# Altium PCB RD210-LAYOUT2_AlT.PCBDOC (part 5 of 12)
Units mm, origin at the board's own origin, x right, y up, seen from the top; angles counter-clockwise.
Board outline 250 x 123 mm, 4 copper layers (TOP, Mid-Layer 1, Mid-Layer 2, BOTTOM), stack 0.711 mm thick; 1043 components, 659 nets, 2786 pads, 1228 vias.
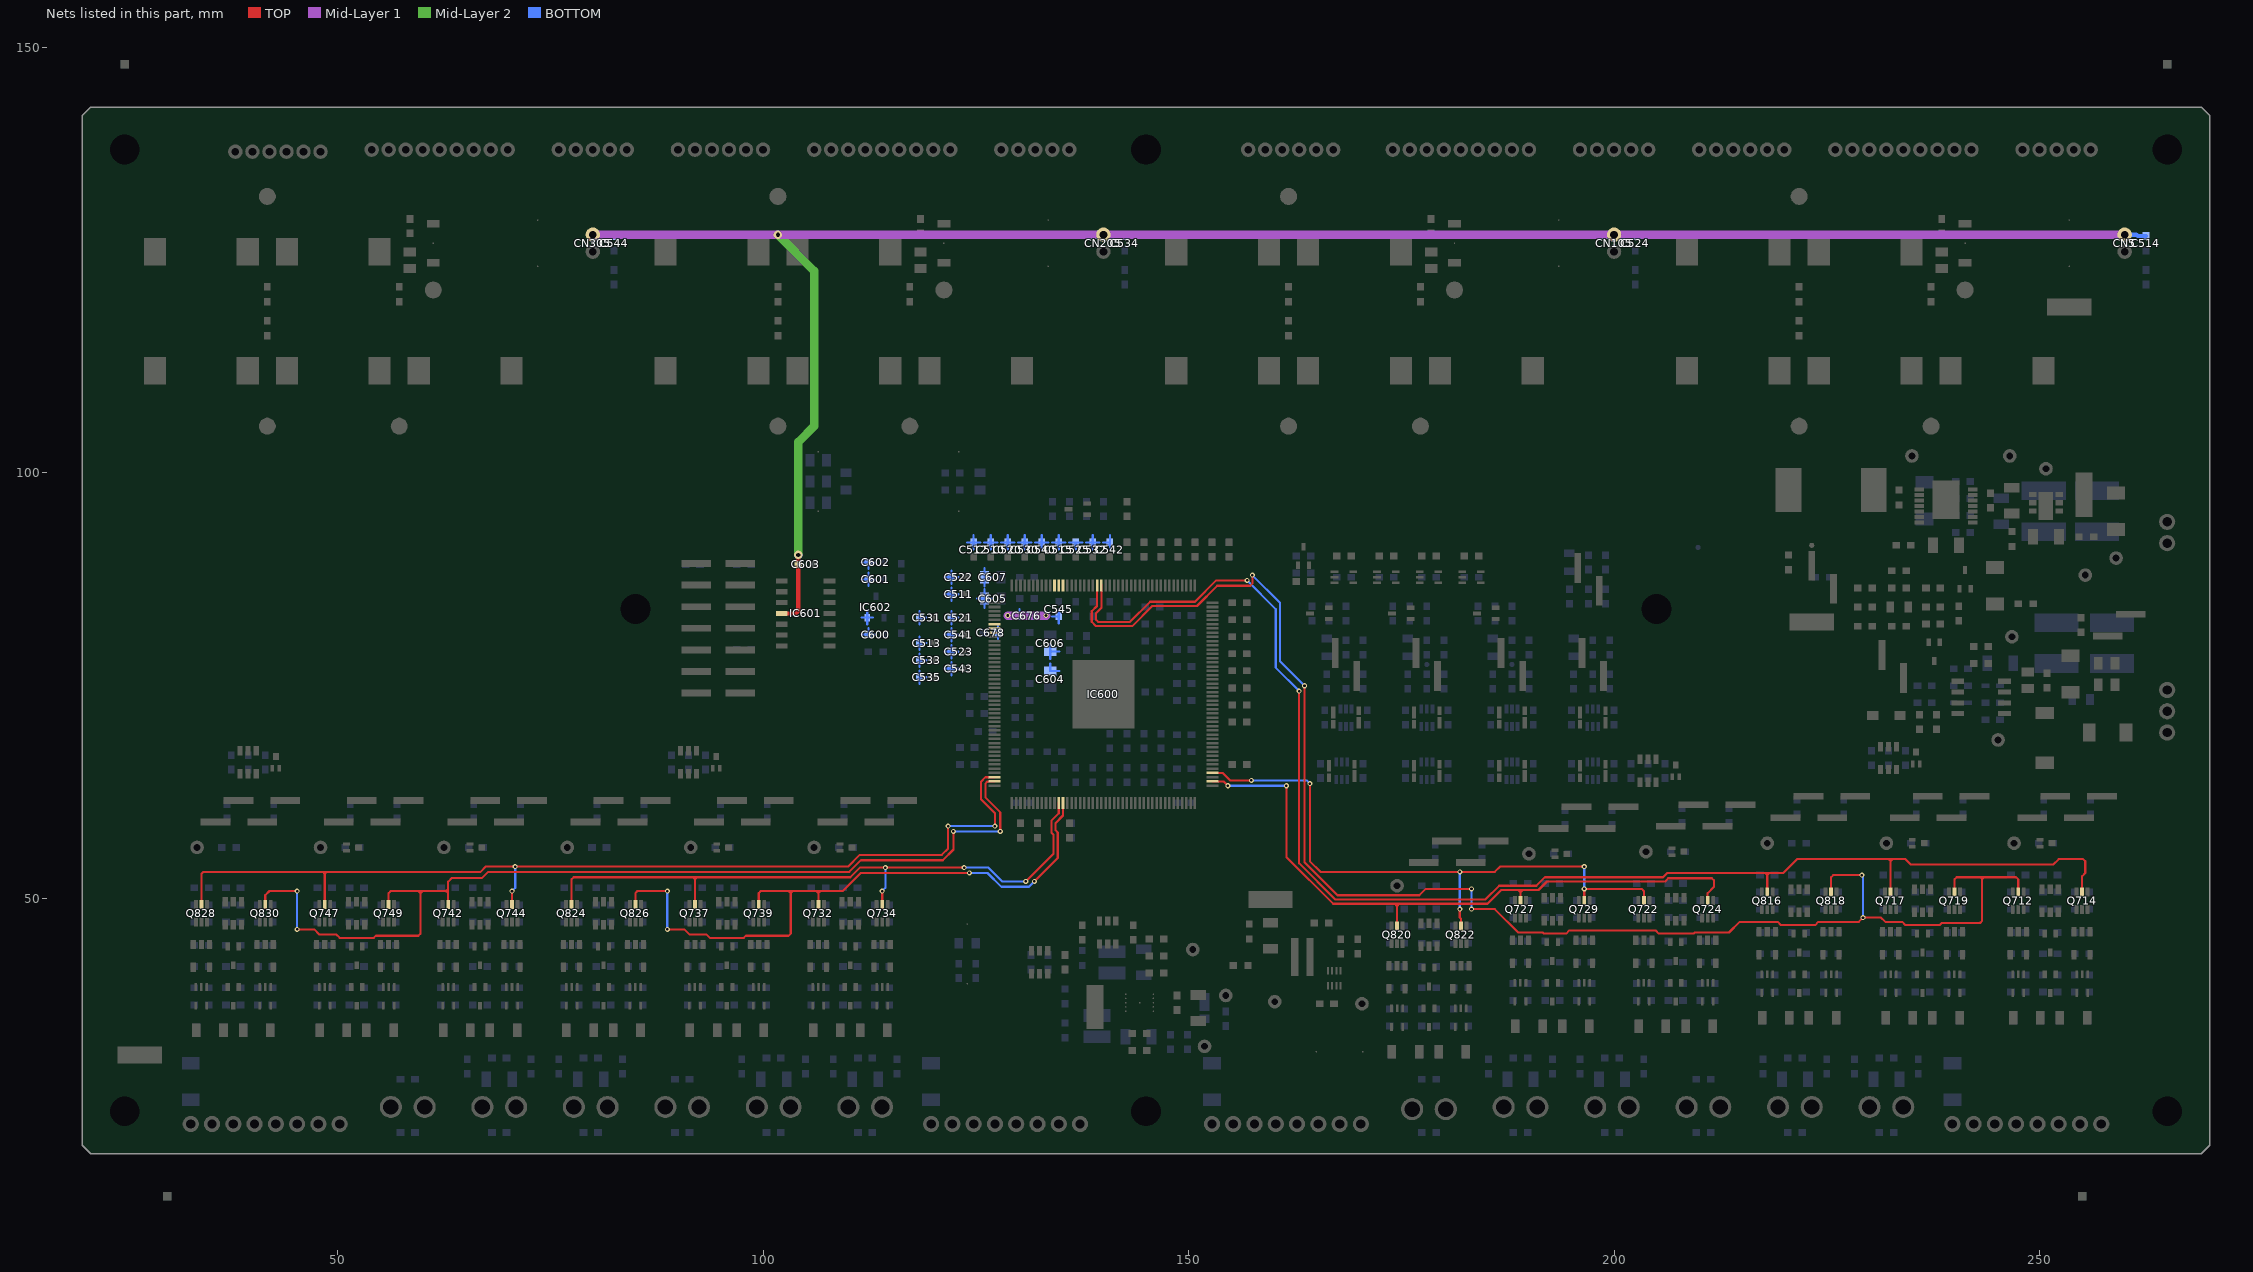
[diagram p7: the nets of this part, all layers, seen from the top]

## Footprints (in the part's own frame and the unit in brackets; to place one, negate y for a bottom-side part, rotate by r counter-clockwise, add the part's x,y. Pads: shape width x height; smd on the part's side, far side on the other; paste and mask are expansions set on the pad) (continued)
S5P_U-2x1.25x1-PX0.65-PY2.1+1 [mm] "KC00080BKP"
  rect 0.3x0.9 smd paste-0.9 mask+0: 1(-0.65,-1.1) 2(0,-1.1) 3(0.65,-1.1) 4(0.65,1.1) 5(-0.65,1.1)
S5P_U-2x1.25x1-PX0.65-PY2.1+2 [mm] "KC00080BKP"
  rect 0.3x0.9 smd paste-0.9 mask+0: 1(-0.65,-1.1) 2(0,-1.1) 3(0.65,-1.1) 4(0.65,1.1) 5(-0.65,1.1)
S5P_U-2x1.25x1-PX0.65-PY2.1+3 [mm] "KC00080BKP"
  rect 0.3x0.9 smd paste-0.9 mask+0: 1(-0.65,-1.1) 2(0,-1.1) 3(0.65,-1.1) 4(0.65,1.1) 5(-0.65,1.1)
S6P_U-2.9x1.6x1.1-PX0.95-PY2.8 [mm] "KC00080BKP"
  rect 0.6x1.1 smd paste-1.1 mask+0: 1(-0.95,-1.35) 2(0,-1.35) 3(0.95,-1.35) 4(0.95,1.35) 5(0,1.35) 6(-0.95,1.35)
S6P_U-2.9x1.6x1.1-PX0.95-PY2.8+1 [mm] "KC00080BKP"
  rect 0.6x1.1 smd paste-1.1 mask+0: 1(-0.95,-1.35) 2(0,-1.35) 3(0.95,-1.35) 4(0.95,1.35) 5(0,1.35) 6(-0.95,1.35)
S7P_U-3x3x0.75-PX0.95-PY3-1 [mm] "KC00080BKP"
  rect 0.6x0.9 smd paste-0.9 mask+0: 1(-0.95,-1.55) 2(0,-1.55) 3(0.95,-1.55) 4(0.95,1.55) 5(0,1.55) 6(-0.95,1.55)
  rect 3.25x1.7 smd paste-3.25 mask+0: 7(-0.375,0)
S8P_U-1.2x2.1x0.6-PX1.6-PY0.5 [mm] "KC00080BKP"
  rect 0.85x0.25 smd paste-0.85 mask+0: 1(-0.875,0.75) 2(-0.875,0.25) 3(-0.875,-0.25) 4(-0.875,-0.75) 5(0.875,-0.75) 6(0.875,-0.25) 7(0.875,0.25) 8(0.875,0.75)
S8P_U-4.9x3.9x1.68-PX1.27-PY6 [mm] "KC00080BKP"
  rect 0.6x1.5 smd paste-1.5 mask+0: 1(-1.905,-2.75) 2(-0.635,-2.75) 3(0.635,-2.75) 4(1.905,-2.75) 5(1.905,2.75) 6(0.635,2.75) 7(-0.635,2.75) 8(-1.905,2.75)
S11P_U-3x3x0.9-PX3-PY0.5 [mil] "KC00080BKP"
  round 7 smd paste-7 mask+0: 1(-63.98,39.37) 2(-63.98,19.69) 3(-63.98,0) 4(-63.98,-19.69) 5(-63.98,-39.37) 6(63.98,-39.37) 7(63.98,-19.69) 8(63.98,0) 9(63.98,19.69) 10(63.98,39.37) 11(0,0)
S14P_CN-17.78x5.08x9.65-PX2.54-PY7.62 [mm] "KC00080BKP"
  rect 0.8x3.45 smd paste-3.45 mask+0: 1(-7.62,-2.59) 2(-7.62,2.59) 3(-5.08,-2.59) 4(-5.08,2.59) 5(-2.54,-2.59) 6(-2.54,2.59) 7(0,-2.59) 8(0,2.59) 9(2.54,-2.59) 10(2.54,2.59) 11(5.08,-2.59) 12(5.08,2.59) 13(7.62,-2.59) 14(7.62,2.59)
S14P_U-8.65x3.9x1.75-PX1.27-PY6 [mm] "KC00080BKP"
  rect 0.6x1.4 smd paste-1.4 mask+0: 1(-3.81,-2.8) 2(-2.54,-2.8) 3(-1.27,-2.8) 4(0,-2.8) 5(1.27,-2.8) 6(2.54,-2.8) 7(3.81,-2.8) 8(3.81,2.8) 9(2.54,2.8) 10(1.27,2.8) 11(0,2.8) 12(-1.27,2.8) 13(-2.54,2.8) 14(-3.81,2.8)
S15P_U-4.4x5x1.2-PX6.4-PY0.65 [mm] "KC00080BKP"
  rect 1.1x0.45 smd paste-1.1 mask+0: 1(-3.15,1.95) 2(-3.15,1.3) 3(-3.15,0.65) 4(-3.15,0) 5(-3.15,-0.65) 6(-3.15,-1.3) 7(-3.15,-1.95) 8(3.15,-1.95) 9(3.15,-1.3) 10(3.15,-0.65) 11(3.15,0) 12(3.15,0.65) 13(3.15,1.3) 14(3.15,1.95)
  rect 3.2x4.55 smd paste-4.55 mask+0: 15(0,0.725)

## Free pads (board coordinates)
  round 0 hole 4 unplated paste-4.2 mask+0: ""(25,15)
  round 0 hole 3.5 unplated paste-3.7 mask+0: ""(25,25) ""(25,138) ""(85,84) ""(145,25) ""(145,138) ""(205,84) ""(265,25) ""(265,138)
  rect 1x1 smd paste-3 mask+0: ""(25,148) ""(30,15) ""(255,15) ""(265,148)
  rect 1x1 smd far side paste-3 mask+0: ""(25,148) ""(30,15) ""(255,15) ""(265,148)
  round 1 smd far side paste-1 mask+0: ""(104.15,90.375)
  round 0.6 smd far side paste-0.6 mask+0: ""(178,77.5) ""(188,77.5) ""(209.875,91.25)
  round 0.6 smd paste-0.6 mask+0: ""(223.23,91.5)
  round 0 hole 4 slot 5 at 0 deg unplated paste-5.2 mask+0: ""(265,15)

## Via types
v1: diameter 0.6, hole 0.3, TOP to BOTTOM, 1134 vias
v2: diameter 1, hole 0.5, TOP to BOTTOM, 94 vias

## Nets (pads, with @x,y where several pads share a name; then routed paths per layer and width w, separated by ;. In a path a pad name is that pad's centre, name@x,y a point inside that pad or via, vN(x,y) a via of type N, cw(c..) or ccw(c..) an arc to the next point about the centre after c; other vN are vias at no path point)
AGND: C510.1 C511.2 C512.1 C513.2 C514.1 C515.1 C520.1 C521.2 C522.2 C523.2 C524.1 C525.1 C530.1 C531.2 C532.1 C533.2 C534.1 C535.2 C540.1 C541.2 C542.1 C543.2 C544.1 C545.1 C600.1 C601.1 C602.1 C603.1 C604.2 C605.1 C606.2 C607.1 C676.1 C678.2 CN5.2 CN105.2 CN205.2 CN305.2 IC600.32 IC600.33 IC600.34 IC600.50 IC600.51 IC600.52 IC601.11 IC602.2 pad.@104.15,90.375 | length 329
  TOP w0.5: IC601.11@102.1,83.5 IC601.11@102.2,83.5 103.875,83.5 104.15,83.775 C603.1@104.15,89.25 v2(104.15,90.375)
  Mid-Layer 1 w1: CN305.2@80,128 v2(101.75,128) CN205.2@140,128 CN105.2@200,128 CN5.2@260,128 ; v1(128.75,83.25) v1(133.25,83.25)
  Mid-Layer 2 w1: v2(101.75,128) 106,123.75 106,105.5 104.15,103.65 v2(104.15,90.375)
  BOTTOM w0.25: 111.575,81 C600.1@112.4,81 ; 111.575,83 IC602.2@112.25,83 ; 111.575,87.5 C601.1@112.4,87.5 ; 111.575,89.5 C602.1@112.4,89.5 ; 112.25,82.175 IC602.2@112.25,83 ; 112.25,83.825 IC602.2@112.25,83 ; 112.4,81.775 C600.1@112.4,81 ; 112.4,86.725 C601.1@112.4,87.5 ; 112.4,88.275 C601.1@112.4,87.5 ; 112.4,88.725 C602.1@112.4,89.5 ; 112.925,83 IC602.2@112.25,83 ; 113.225,81 C600.1@112.4,81 ; 113.225,87.5 C601.1@112.4,87.5 ; 113.225,89.5 C602.1@112.4,89.5 ; 118.4,75.225 C535.2@118.4,76 ; 118.4,76.775 C535.2@118.4,76 ; 118.4,77.225 C533.2@118.4,78 ; 118.4,78.775 C533.2@118.4,78 ; 118.4,79.225 C513.2@118.4,80 ; 118.4,80.775 C513.2@118.4,80 ; 118.4,82.225 C531.2@118.4,83 ; 118.4,83.775 C531.2@118.4,83 ; 119.225,76 C535.2@118.4,76 ; 119.225,78 C533.2@118.4,78 ; 119.225,80 C513.2@118.4,80 ; 119.225,83 C531.2@118.4,83 ; 121.325,77 C543.2@122.15,77 ; 121.325,79 C523.2@122.15,79 ; 121.325,81 C541.2@122.15,81 ; 121.325,85.75 C511.2@122.15,85.75 ; 121.325,87.75 C522.2@122.15,87.75 ; 122.15,76.225 C543.2@122.15,77 ; 122.15,77.775 C543.2@122.15,77 ; 122.15,78.225 C523.2@122.15,79 ; 122.15,79.775 C523.2@122.15,79 ; 122.15,80.225 C541.2@122.15,81 ; 122.15,81.775 C541.2@122.15,81 ; 122.15,82.225 C521.2@122.15,83 ; 122.15,83.775 C521.2@122.15,83 ; 122.15,84.975 C511.2@122.15,85.75 ; 122.15,86.525 C511.2@122.15,85.75 ; 122.15,86.975 C522.2@122.15,87.75 ; 122.15,88.525 C522.2@122.15,87.75 ; 122.975,77 C543.2@122.15,77 ; 122.975,79 C523.2@122.15,79 ; 122.975,81 C541.2@122.15,81 ; 122.975,83 C521.2@122.15,83 ; 122.975,85.75 C511.2@122.15,85.75 ; 122.975,87.75 C522.2@122.15,87.75 ; 123.975,91.85 C512.1@124.75,91.85 ; 124.75,91.025 C512.1@124.75,91.85 ; 124.75,92.675 C512.1@124.75,91.85 ; 125.125,85.25 C605.1@126.025,85.25 ; 125.525,91.85 C512.1@124.75,91.85 ; 125.975,91.85 C510.1@126.75,91.85 ; 126.025,84.15 C605.1@126.025,85.25 ; 126.025,86.35 C605.1@126.025,85.25 ; 126.025,86.65 C607.1@126.025,87.75 ; 126.025,88.85 C607.1@126.025,87.75 ; 126.75,91.025 C510.1@126.75,91.85 ; 126.75,92.675 C510.1@126.75,91.85 ; 126.775,81.25 C678.2@127.6,81.25 ; 126.925,85.25 C605.1@126.025,85.25 ; 126.925,87.75 C607.1@126.025,87.75 ; 127.525,91.85 C510.1@126.75,91.85 ; 127.6,80.475 C678.2@127.6,81.25 ; 127.6,82.025 C678.2@127.6,81.25 ; 127.975,91.85 C520.1@128.75,91.85 ; 128.75,91.025 C520.1@128.75,91.85 ; 128.75,92.675 C520.1@128.75,91.85 ; 129.325,83.25 C676.1@130.15,83.25 ; 129.525,91.85 C520.1@128.75,91.85 ; 129.975,91.85 C530.1@130.75,91.85 ; 130.15,84.025 C676.1@130.15,83.25 ; 130.75,91.025 C530.1@130.75,91.85 ; 130.75,92.675 C530.1@130.75,91.85 ; 130.975,83.25 C676.1@130.15,83.25 ; 131.525,91.85 C530.1@130.75,91.85 ; 131.975,91.85 C540.1@132.75,91.85 ; 132.75,91.025 C540.1@132.75,91.85 ; 132.75,92.675 C540.1@132.75,91.85 ; 133.525,91.85 C540.1@132.75,91.85 ; 133.75,77.625 C604.2@133.75,76.725 134.85,76.725 ; 133.75,78.125 C606.2@133.75,79.025 ; 133.75,79.925 C606.2@133.75,79.025 ; 133.975,83.15 C545.1@134.75,83.15 ; 133.975,91.85 C515.1@134.75,91.85 ; 134.75,82.325 C545.1@134.75,83.15 ; 134.75,83.975 C545.1@134.75,83.15 ; 134.75,91.025 C515.1@134.75,91.85 ; 134.75,92.675 C515.1@134.75,91.85 ; 134.85,79.025 C606.2@133.75,79.025 ; 135.525,91.85 C515.1@134.75,91.85 ; 135.975,91.85 C525.1@136.75,91.85 ; 136.75,91.025 C525.1@136.75,91.85 ; 137.525,91.85 C525.1@136.75,91.85 ; 137.975,91.85 C532.1@138.75,91.85 ; 138.75,91.025 C532.1@138.75,91.85 ; 138.75,92.675 C532.1@138.75,91.85 ; 139.525,91.85 C532.1@138.75,91.85 ; 139.975,91.85 C542.1@140.75,91.85 ; 140.75,91.025 C542.1@140.75,91.85 ; 140.75,92.675 C542.1@140.75,91.85
  BOTTOM w0.5: CN305.2@80,128 81.475,128 81.625,127.85 C544.1@82.5,127.85 ; CN205.2@140,128 141.475,128 141.625,127.85 C534.1@142.5,127.85 ; CN105.2@200,128 201.475,128 201.625,127.85 C524.1@202.5,127.85 ; CN5.2@260,128 261.375,128 261.525,127.85 C514.1@262.5,127.85
BIAS_1_ON-1: IC600.23 Q714.5 Q717.5 Q816.5 | length 167.5
  TOP w0.25: IC600.23@139.75,86.8 139.75,84.125 139.125,83.5 139.125,82.725 139.15,82.725 139.375,82.5 143.125,82.5 145.5,84.875 150.75,84.875 153.25,87.375 v1(156.875,87.375) ; v1(163,74.375) 163,54.125 167.25,49.875 184.875,49.875 186.5,51.5 190.875,51.5 191.875,52.5 205.75,52.5 206.25,53 217.75,53 ; Q816.5@218,50.775 218,52.75 ; Q717.5@232.5,50.775 232.5,54.375 ; Q714.5@255,50.775 255,52.625 255.375,53 255.375,54.375 255.125,54.625 252.25,54.625 251.625,54 234.875,54 234.25,54.625 232.75,54.625 ; 217.75,53 218,52.75 ; 217.75,53 218.25,53 ; 218,52.75 218.25,53 ; 218.25,53 219.875,53 221.5,54.625 232.25,54.625 ; 232.25,54.625 232.5,54.375 ; 232.25,54.625 232.75,54.625 ; 232.5,54.375 232.75,54.625
  BOTTOM w0.25: v1(156.875,87.375) 160.25,84 160.25,77.125 v1(163,74.375)
BIAS_1_ON-2: IC600.134 Q724.5 Q727.5 Q820.5 | length 78.6
  TOP w0.25: IC600.134@152.8,63.75 154.15,63.75 154.625,63.275 v1(154.625,63.25) ; v1(161.5,63.25) 161.5,54.875 167,49.375 174.25,49.375 ; Q820.5@174.5,46.775 174.5,49.125 ; Q727.5@189,49.775 189,50.75 ; Q724.5@211,49.775 211,50.625 211.75,51.375 211.75,52.125 211.5,52.375 206.375,52.375 206,52 192.125,52 191.125,51 189.25,51 ; 174.25,49.375 174.75,49.375 ; 174.25,49.375 174.5,49.125 ; 174.5,49.125 174.75,49.375 ; 174.75,49.375 185.125,49.375 186.75,51 188.75,51 ; 188.75,51 189.25,51 ; 188.75,51 189,50.75 ; 189,50.75 189.25,51
  BOTTOM w0.25: v1(154.625,63.25) v1(161.5,63.25)
BIAS_1_ON-3: IC600.100 Q734.5 Q737.5 Q824.5 | length 76.8
  TOP w0.25: Q824.5@77.5,49.275 77.5,52.25 77.75,52.5 91.75,52.5 ; Q737.5@92,49.275 92,52.25 ; Q734.5@114,49.275 v1(114,50.875) ; v1(123.625,53.625) v1(114.375,53.625) 111.375,53.625 110.25,52.5 92.25,52.5 ; v1(130.875,52) 134.125,55.25 134.125,57.5 133.875,57.75 133.875,59.125 134.75,60 IC600.100@134.75,61.2 ; 91.75,52.5 92,52.25 ; 91.75,52.5 92.25,52.5 ; 92,52.25 92.25,52.5
  BOTTOM w0.25: v1(114,50.875) 114.375,51.25 v1(114.375,53.625) ; v1(123.625,53.625) 126.5,53.625 128.125,52 v1(130.875,52)
BIAS_1_ON-4: IC600.86 Q744.5 Q747.5 Q828.5 | length 117.4
  TOP w0.25: Q828.5@34,49.275 34,52.875 34.25,53.125 48.25,53.125 ; Q747.5@48.5,49.275 48.5,52.875 ; Q744.5@70.5,49.275 v1(70.5,50.875) ; v1(121.75,58.5) 121.75,55.875 121,55.125 111.375,55.125 110,53.75 v1(70.875,53.75) 67.433,53.75 66.808,53.125 48.75,53.125 ; IC600.86@127.2,64.25 126.125,64.25 125.625,63.75 125.625,61.625 127.25,60 v1(127.25,58.5) ; 48.25,53.125 48.5,52.875 ; 48.25,53.125 48.75,53.125 ; 48.5,52.875 48.75,53.125
  BOTTOM w0.25: v1(70.5,50.875) 70.875,51.25 v1(70.875,53.75) ; v1(121.75,58.5) v1(127.25,58.5)
BIAS_2_ON-1: IC600.24 Q712.5 Q719.5 Q818.5 | length 176.8
  TOP w0.25: IC600.24@139.25,86.8 139.25,84.375 138.625,83.75 138.625,82.5 139.125,82 143.375,82 145.75,84.375 151,84.375 153.375,86.75 157.25,86.75 157.5,87 v1(157.5,88) ; v1(163.625,75) 163.625,54.25 167.5,50.375 177.125,50.375 177.875,51.125 v1(183.25,51.125) ; v1(183.25,48.75) 186,48.75 188.75,46 191.625,46 191.75,45.875 194.375,45.875 194.75,46.25 204.875,46.25 205.25,45.875 209.375,45.875 209.5,46 213.5,46 214.75,47.25 219.25,47.25 219.625,46.875 223.625,46.875 224,47.25 228.75,47.25 v1(229.25,47.75) 231.375,47.75 231.875,47.25 233.875,47.25 234.25,46.875 238.25,46.875 238.5,47.125 243,47.125 243.25,47.375 243.25,52.25 ; Q818.5@225.5,50.775 225.5,52.5 225.75,52.75 v1(229.125,52.75) ; Q719.5@240,50.775 240,52.25 240.25,52.5 243,52.5 ; Q712.5@247.5,50.775 247.5,52.25 247.25,52.5 243.5,52.5 ; 243,52.5 243.25,52.25 ; 243,52.5 243.5,52.5 ; 243.25,52.25 243.5,52.5
  BOTTOM w0.25: v1(157.5,88) 160.75,84.75 160.75,77.875 v1(163.625,75) ; v1(183.25,48.75) v1(183.25,51.125) ; v1(229.125,52.75) 229.25,52.625 v1(229.25,47.75)
BIAS_2_ON-2: IC600.136 Q722.5 Q729.5 Q822.5 | length 72.7
  TOP w0.25: IC600.136@152.8,64.75 154,64.75 154.875,63.875 v1(157.375,63.875) ; v1(164.25,63.5) 164.25,54.375 165.5,53.125 v1(181.875,53.125) 186,53.125 186.625,53.75 v1(196.5,53.75) ; v1(181.875,48.75) 181.875,47.75 182,47.625 Q822.5@182,46.775 ; Q729.5@196.5,49.775 v1(196.5,51.125) 203.25,51.125 203.5,50.875 Q722.5@203.5,49.775
  BOTTOM w0.25: v1(157.375,63.875) 163.875,63.875 v1(164.25,63.5) ; v1(181.875,48.75) v1(181.875,53.125) ; v1(196.5,51.125) v1(196.5,53.75)
BIAS_2_ON-3: IC600.101 Q732.5 Q739.5 Q826.5 | length 78.8
  TOP w0.25: Q826.5@85,49.275 85,50.625 85.25,50.875 v1(88.75,50.875) ; v1(88.75,46.375) 90.75,46.375 91.375,45.75 93.375,45.75 93.75,45.375 97.75,45.375 98,45.625 103,45.625 103.25,45.875 103.25,50.625 ; Q739.5@99.5,49.275 99.5,50.625 99.75,50.875 103,50.875 ; Q732.5@106.5,49.275 106.5,50.625 ; v1(124.25,53) 111.5,53 109.375,50.875 106.75,50.875 ; v1(131.875,52) 134.625,54.75 134.625,57.75 134.375,58 134.375,58.875 135.25,59.75 IC600.101@135.25,61.2 ; 103,50.875 103.5,50.875 ; 103,50.875 103.25,50.625 ; 103.25,50.625 103.5,50.875 ; 103.5,50.875 106.25,50.875 ; 106.25,50.875 106.75,50.875 ; 106.25,50.875 106.5,50.625 ; 106.5,50.625 106.75,50.875
  BOTTOM w0.25: v1(88.75,46.375) v1(88.75,50.875) ; v1(124.25,53) 126.375,53 128,51.375 131.25,51.375 v1(131.875,52)
BIAS_2_ON-4: IC600.87 Q742.5 Q749.5 Q830.5 | length 117.8
  TOP w0.25: Q830.5@41.5,49.275 41.5,50.375 42,50.875 v1(45.25,50.875) ; v1(45.25,46.375) 47.25,46.375 47.875,45.75 49.875,45.75 50.25,45.375 54.25,45.375 54.5,45.625 59.5,45.625 59.75,45.875 59.75,50.625 ; Q749.5@56,49.275 56,50.625 56.25,50.875 59.5,50.875 ; Q742.5@63,49.275 63,50.625 ; v1(122.375,57.875) 122.375,55.75 121.125,54.5 111.5,54.5 110.125,53.125 67.697,53.125 66.99,52.418 63.444,52.418 63,51.973 63,51.125 ; IC600.87@127.2,63.75 126.375,63.75 126.125,63.5 126.125,61.875 127.875,60.125 v1(127.875,57.875) ; 59.5,50.875 59.75,50.625 ; 59.5,50.875 60,50.875 ; 59.75,50.625 60,50.875 ; 60,50.875 62.75,50.875 ; 62.75,50.875 63,50.625 ; 62.75,50.875 63,51.125 ; 63,50.625 63,51.125
  BOTTOM w0.25: v1(45.25,46.375) v1(45.25,50.875) ; v1(122.375,57.875) v1(127.875,57.875)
